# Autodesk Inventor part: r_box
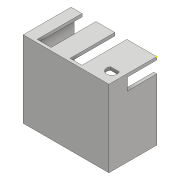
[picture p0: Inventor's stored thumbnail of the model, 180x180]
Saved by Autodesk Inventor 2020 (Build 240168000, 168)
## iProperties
Created: 2022-05
Part Number: r_box
Material: Generic
Document SubType Name: Modeling
Designer: xmls36
Density: 1 g/cm^3
Appearance: Default
Author: xmls36
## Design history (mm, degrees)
sketch "Sketch1"
  geometry: L1 (0, 0)-(86, 0); L2 (86, 0)-(86, -77); L3 (86, -77)-(0, -77); L4 (0, -77)-(0, 0); L5 (83, -3)-(3, -3); L6 (3, -3)-(3, -74); L7 (3, -74)-(83, -74); L8 (83, -74)-(83, -3)
  constraints: 16 end point, 4 parallel, 2 horizontal, 2 perpendicular
  dimensions: "d7" = 86 distance of L2.end L3.end; "d8" = 80 distance of L6.end L7.end; "d9" = 3 distance between parallel lines of L8 L2; "d10" = 77 distance of L1.end L2.end; "d11" = 71 distance of L7.end L5.start; "d12" = 3 distance between parallel lines of L3 L7
extrude "Extrusion1" new body sketch "Sketch1" distance "d13" = 48; taper "d14" = 0 deg
sketch "Sketch2"
  geometry: 1 further point
sketch "Sketch3"
  geometry: L1 (-83, 3)-(-3, 3); L2 (-3, 3)-(-3, 74); L3 (-3, 74)-(-83, 74); L4 (-83, 74)-(-83, 3); L5 (-86, 77)-(-86, 0) reference; L6 (0, 77)-(-86, 77) reference; 1 further point
  constraints: 8 end point, 2 parallel, 1 horizontal, 1 perpendicular
  dimensions: "d15" = 80 distance of L3.end L2.end; "d16" = 71 distance of L3.end L1.start; "d17" = 3 distance between parallel lines of L5 L4; "d18" = 3 distance between parallel lines of L6 L3
extrude "Extrusion2" cut sketch "Sketch3" distance "d19" = 45; taper "d20" = 0 deg
sketch "Sketch6"
  geometry: L1 (3, 48)-(15, 48); L2 (15, 48)-(15, 18.5); L3 (15, 18.5)-(3, 18.5); L4 (3, 18.5)-(3, 48); L5 (0, 0)-(77, 0) reference; L6 (0, 48)-(77, 48) reference; L7 (0, 0)-(0, 48) reference
  constraints: 8 end point, 2 parallel, 1 horizontal, 1 perpendicular
  dimensions: "d21" = 18.5 distance between parallel lines of L5 L3; "d22" = 0 distance between parallel lines of L6 L1; "d23" = 3 distance between parallel lines of L7 L4; "d24" = 12 distance between parallel lines of L4 L2
extrude "Extrusion3" cut sketch "Sketch6" distance "d25" = 3; taper "d26" = 0 deg
sketch "Sketch8"
  geometry: L1 (-3, 3)-(-83, 3) reference; L2 (-86, 0)-(0, 0) reference; L3 (-75, 3)-(-61, 3); L4 (-61, 3)-(-61, 0); L5 (-61, 0)-(-75, 0); L6 (-75, 0)-(-75, 3); L7 (-86, 77)-(-86, 0) reference; L8 (-42, 3)-(-30, 3); L9 (-30, 3)-(-30, 0); L10 (-30, 0)-(-42, 0); L11 (-42, 0)-(-42, 3); 4 further points
  constraints: 16 end point, 4 parallel, 4 point on line, 2 horizontal, 2 perpendicular
  dimensions: "d29" = 11 distance between parallel lines of L7 L6; "d31" = 19 distance between parallel lines of L4 L11; "d32" = 12 distance between parallel lines of L11 L9; "d33" = 14 distance between parallel lines of L6 L4
extrude "Extrusion4" cut sketch "Sketch8" distance "d34" = 45; taper "d35" = 0 deg
sketch "Sketch9"
  geometry: L1 (0, 0)-(86, 0) reference; L2 (86, 0)-(86, 48) reference; L3 (71.631, 16)-(80.369, 16); A1 r 5.3 centre (76, 13) between (71.631, 16) and (80.369, 16)
  constraints: 2 end point, 2 point on circle, 1 centre point, 1 horizontal
  dimensions: "d36" = 13 distance from line of L1 A1.centre; "d37" = 10.6 diameter of A1; "d38" = 10 distance from line of L2 A1.centre; "d39" = 3 distance from line of L3 A1.centre
extrude "Extrusion5" cut sketch "Sketch9" distance "d40" = 3; taper "d41" = 0 deg
body "Solid1"
